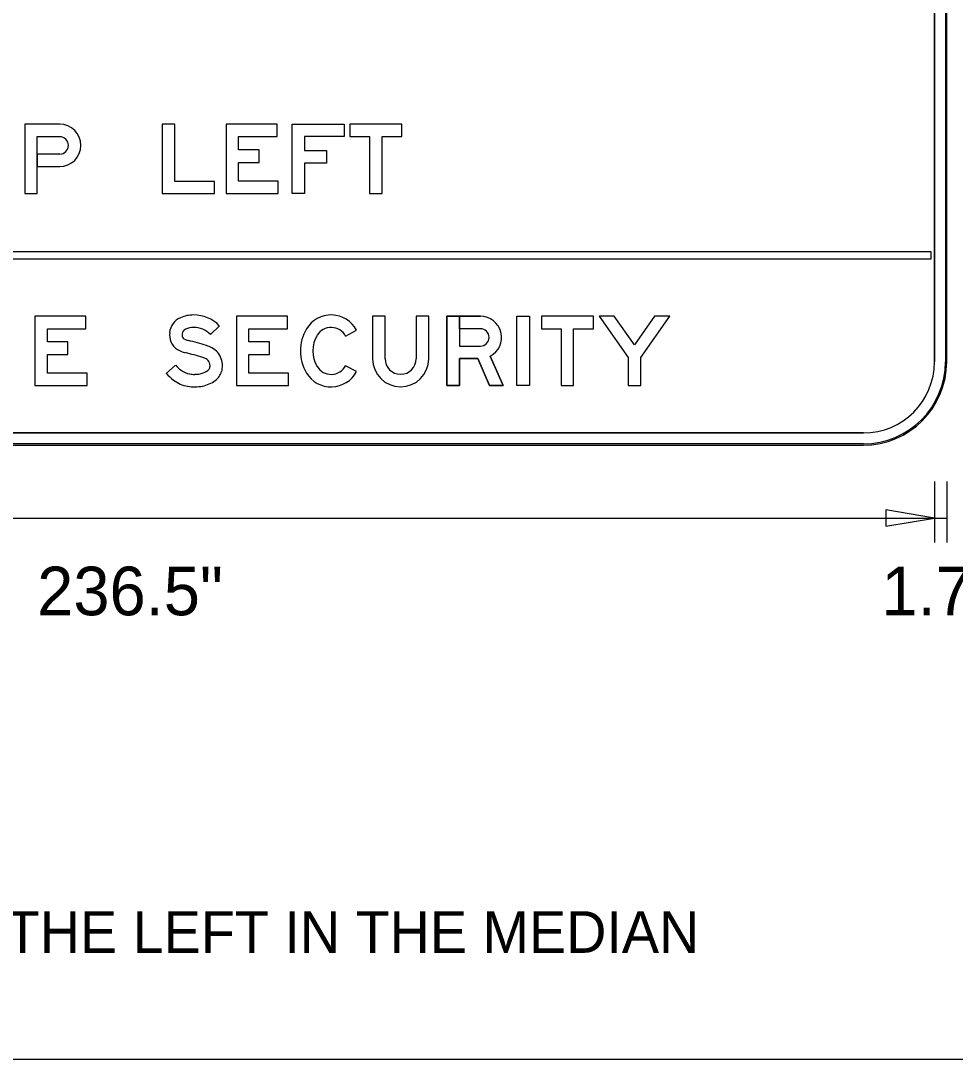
# Model space of a CAD drawing. Extents: x 17890071 to 17890754, y 17897628 to 17897992.
# Drawn here: x 17890123.33 to 17890134.54, y 17897797.14 to 17897809.61 of the extents above; entities that cross this region are included whole.
import ezdxf

# ---------------------------------------------------------------- set-up
doc = ezdxf.new("R2010")
doc.units = 0
for name, color, linetype in [('GSBWFill', 7, 'Continuous'), ('GSColorFill', 7, 'Continuous'), ('GSDims', 7, 'Continuous'), ('GSOutline', 7, 'Continuous'), ('SheetLinesMisc2_dp', 7, 'Continuous')]:
    doc.layers.add(name, color=color, linetype=linetype)

msp = doc.modelspace()

# ---------------------------------------------------------------- linework, layer by layer
at = {"layer": 'GSBWFill'}
for p, q in [((17890134.293, 17897813.514), (17890134.293, 17897805.514)), ((17890134.439, 17897805.514), (17890134.439, 17897813.514)), ((17890123.528, 17897808.216), (17890123.798, 17897808.216)), ((17890134.253, 17897806.832), (17890114.587, 17897806.832)), ((17890134.253, 17897806.749), (17890134.253, 17897806.832)), ((17890114.587, 17897806.749), (17890134.253, 17897806.749)), ((17890128.076, 17897806.061), (17890128.076, 17897805.551)), ((17890127.227, 17897805.822), (17890127.359, 17897805.892)), ((17890127.359, 17897805.397), (17890127.227, 17897805.467)), ((17890127.227, 17897805.467), (17890127.227, 17897805.467)), ((17890133.439, 17897804.66), (17890115.441, 17897804.66)), ((17890115.441, 17897804.514), (17890133.439, 17897804.514))]:
    msp.add_line(p, q, dxfattribs=at)
for points in [[(17890123.798, 17897808.366), (17890123.378, 17897808.366), (17890123.378, 17897807.532), (17890123.528, 17897807.532), (17890123.528, 17897808.216)], [(17890123.798, 17897808.007), (17890123.528, 17897808.007), (17890123.528, 17897807.857), (17890123.798, 17897807.857)], [(17890127.701, 17897805.551), (17890127.701, 17897806.061), (17890127.551, 17897806.061), (17890127.551, 17897805.551)], [(17890128.226, 17897805.551), (17890128.226, 17897806.061), (17890128.076, 17897806.061)], [(17890128.964, 17897805.582), (17890129.118, 17897805.228), (17890128.954, 17897805.228), (17890128.813, 17897805.553), (17890128.593, 17897805.553), (17890128.593, 17897805.228), (17890128.443, 17897805.228), (17890128.443, 17897806.061), (17890128.593, 17897806.061), (17890128.593, 17897805.703), (17890128.845, 17897805.703)], [(17890128.593, 17897805.911), (17890128.593, 17897806.061), (17890128.845, 17897806.061)], [(17890125.713, 17897805.946), (17890125.605, 17897805.841)], [(17890128.845, 17897805.911), (17890128.593, 17897805.911)], [(17890125.076, 17897805.375), (17890125.189, 17897805.474)]]:
    msp.add_lwpolyline(points, dxfattribs=at)
for points in [[(17890125.653, 17897807.532), (17890125.653, 17897807.678), (17890125.178, 17897807.678), (17890125.178, 17897808.366), (17890125.028, 17897808.366), (17890125.028, 17897807.532)], [(17890126.419, 17897807.682), (17890125.944, 17897807.682), (17890125.944, 17897807.906), (17890126.19, 17897807.906), (17890126.19, 17897808.056), (17890125.944, 17897808.056), (17890125.944, 17897808.216), (17890126.407, 17897808.216), (17890126.407, 17897808.366), (17890125.794, 17897808.366), (17890125.794, 17897807.532), (17890126.419, 17897807.532)], [(17890126.736, 17897807.899), (17890126.736, 17897807.532), (17890126.586, 17897807.532), (17890126.586, 17897808.366), (17890127.211, 17897808.366), (17890127.211, 17897808.216), (17890126.736, 17897808.216), (17890126.736, 17897808.049), (17890126.998, 17897808.049), (17890126.998, 17897807.899)], [(17890127.278, 17897808.216), (17890127.515, 17897808.216), (17890127.515, 17897807.532), (17890127.665, 17897807.532), (17890127.665, 17897808.216), (17890127.903, 17897808.216), (17890127.903, 17897808.366), (17890127.278, 17897808.366)], [(17890124.126, 17897805.378), (17890123.651, 17897805.378), (17890123.651, 17897805.602), (17890123.897, 17897805.602), (17890123.897, 17897805.752), (17890123.651, 17897805.752), (17890123.651, 17897805.911), (17890124.113, 17897805.911), (17890124.113, 17897806.061), (17890123.501, 17897806.061), (17890123.501, 17897805.228), (17890124.126, 17897805.228)], [(17890126.543, 17897805.378), (17890126.068, 17897805.378), (17890126.068, 17897805.602), (17890126.313, 17897805.602), (17890126.313, 17897805.752), (17890126.068, 17897805.752), (17890126.068, 17897805.911), (17890126.53, 17897805.911), (17890126.53, 17897806.061), (17890125.918, 17897806.061), (17890125.918, 17897805.228), (17890126.543, 17897805.228)], [(17890129.284, 17897805.228), (17890129.284, 17897806.061), (17890129.434, 17897806.061), (17890129.434, 17897805.228)], [(17890129.576, 17897805.911), (17890129.813, 17897805.911), (17890129.813, 17897805.228), (17890129.963, 17897805.228), (17890129.963, 17897805.911), (17890130.201, 17897805.911), (17890130.201, 17897806.061), (17890129.576, 17897806.061)], [(17890130.768, 17897805.565), (17890131.118, 17897806.061), (17890130.934, 17897806.061), (17890130.693, 17897805.719), (17890130.451, 17897806.061), (17890130.268, 17897806.061), (17890130.618, 17897805.565), (17890130.618, 17897805.228), (17890130.768, 17897805.228)]]:
    msp.add_lwpolyline(points, close=True, dxfattribs=at)
for centre, radius, start, end in [((17890125.405, 17897805.678), 0.398, 90, 113.3248), ((17890125.405, 17897805.645), 0.431, 44.4342, 90), ((17890127.054, 17897805.73), 0.346, 28.0265, 148.7499), ((17890125.333, 17897805.843), 0.218, 113.3248, 174.1421), ((17890128.845, 17897805.807), 0.254, 297.837, 90), ((17890125.354, 17897805.841), 0.238, 174.1421, 201.2247), ((17890125.354, 17897805.841), 0.0882, 174.1421, 201.2247), ((17890125.333, 17897805.843), 0.0679, 113.3248, 174.1421), ((17890125.405, 17897805.678), 0.248, 90, 113.3248), ((17890125.405, 17897805.645), 0.281, 44.4342, 90), ((17890127.195, 17897805.644), 0.51, 148.7499, 211.2501), ((17890127.195, 17897805.644), 0.36, 148.7499, 211.2501), ((17890127.054, 17897805.73), 0.196, 28.0265, 148.7499), ((17890128.845, 17897805.807), 0.104, 270, 90), ((17890125.305, 17897805.822), 0.186, 201.2247, 240.1812), ((17890125.305, 17897805.822), 0.0363, 201.2247, 240.1812), ((17890125.391, 17897805.972), 0.209, 240.1812, 256.1067), ((17890124.37, 17897801.843), 4.045, 72.8961, 76.1067), ((17890125.442, 17897805.326), 0.4, 63.0108, 72.8961), ((17890125.391, 17897805.972), 0.359, 240.1812, 256.1067), ((17890124.37, 17897801.843), 3.895, 72.8961, 76.1067), ((17890125.522, 17897805.485), 0.222, 39.5561, 63.0108), ((17890125.502, 17897805.467), 0.249, 0, 39.5561), ((17890125.515, 17897805.755), 0.43, 220.8202, 232.6492), ((17890125.442, 17897805.326), 0.25, 63.0108, 72.8961), ((17890125.522, 17897805.485), 0.0724, 39.5561, 63.0108), ((17890125.502, 17897805.467), 0.0993, 0, 39.5561), ((17890125.508, 17897805.467), 0.0932, 343.4972, 0), ((17890125.508, 17897805.467), 0.243, 343.4972, 0), ((17890127.054, 17897805.559), 0.196, 211.2501, 331.9735), ((17890127.888, 17897805.551), 0.337, 180, 0), ((17890127.888, 17897805.551), 0.187, 180, 0), ((17890133.439, 17897805.514), 1, 270, 0), ((17890133.439, 17897805.514), 0.854, 270, 0), ((17890125.515, 17897805.755), 0.58, 220.8202, 232.6492), ((17890125.394, 17897805.597), 0.231, 232.6492, 260.7349), ((17890125.42, 17897805.751), 0.388, 260.7349, 270), ((17890125.42, 17897805.67), 0.306, 270, 281.6446), ((17890125.432, 17897805.609), 0.245, 281.6446, 306.0677), ((17890125.543, 17897805.457), 0.0563, 306.0677, 343.4972), ((17890125.543, 17897805.457), 0.206, 306.0677, 343.4972), ((17890127.054, 17897805.559), 0.346, 211.2501, 331.9735), ((17890125.394, 17897805.597), 0.381, 232.6492, 260.7349), ((17890125.42, 17897805.751), 0.538, 260.7349, 270), ((17890125.42, 17897805.67), 0.456, 270, 281.6446), ((17890125.432, 17897805.609), 0.395, 281.6446, 306.0677)]:
    msp.add_arc(centre, radius, start, end, dxfattribs=at)
for major_axis in [(0, 0.254), (0, 0.104)]:
    msp.add_ellipse((17890123.798, 17897808.111), major_axis=major_axis, ratio=0.999997, start_param=3.141593, end_param=6.283185, dxfattribs=at)
at = {"layer": 'GSColorFill'}
for p, q in [((17890134.293, 17897813.514), (17890134.293, 17897805.514)), ((17890134.425, 17897813.514), (17890134.425, 17897805.514)), ((17890134.439, 17897805.514), (17890134.439, 17897813.514)), ((17890134.439, 17897805.514), (17890134.439, 17897813.514)), ((17890134.439, 17897805.514), (17890134.439, 17897813.514)), ((17890123.528, 17897808.216), (17890123.798, 17897808.216)), ((17890134.253, 17897806.832), (17890114.587, 17897806.832)), ((17890134.253, 17897806.749), (17890134.253, 17897806.832)), ((17890114.587, 17897806.749), (17890134.253, 17897806.749)), ((17890128.076, 17897806.061), (17890128.076, 17897805.551)), ((17890127.227, 17897805.822), (17890127.359, 17897805.892)), ((17890127.359, 17897805.397), (17890127.227, 17897805.467)), ((17890127.227, 17897805.467), (17890127.227, 17897805.467)), ((17890133.439, 17897804.66), (17890115.441, 17897804.66)), ((17890133.439, 17897804.529), (17890115.439, 17897804.529)), ((17890115.439, 17897804.514), (17890133.439, 17897804.514)), ((17890115.439, 17897804.514), (17890133.439, 17897804.514)), ((17890115.441, 17897804.514), (17890133.439, 17897804.514))]:
    msp.add_line(p, q, dxfattribs=at)
for points in [[(17890123.798, 17897808.366), (17890123.378, 17897808.366), (17890123.378, 17897807.532), (17890123.528, 17897807.532), (17890123.528, 17897808.216)], [(17890123.798, 17897808.007), (17890123.528, 17897808.007), (17890123.528, 17897807.857), (17890123.798, 17897807.857)], [(17890127.701, 17897805.551), (17890127.701, 17897806.061), (17890127.551, 17897806.061), (17890127.551, 17897805.551)], [(17890128.226, 17897805.551), (17890128.226, 17897806.061), (17890128.076, 17897806.061)], [(17890128.964, 17897805.582), (17890129.118, 17897805.228), (17890128.954, 17897805.228), (17890128.813, 17897805.553), (17890128.593, 17897805.553), (17890128.593, 17897805.228), (17890128.443, 17897805.228), (17890128.443, 17897806.061), (17890128.593, 17897806.061), (17890128.593, 17897805.703), (17890128.845, 17897805.703)], [(17890128.593, 17897805.911), (17890128.593, 17897806.061), (17890128.845, 17897806.061)], [(17890125.713, 17897805.946), (17890125.605, 17897805.841)], [(17890128.845, 17897805.911), (17890128.593, 17897805.911)], [(17890125.076, 17897805.375), (17890125.189, 17897805.474)]]:
    msp.add_lwpolyline(points, dxfattribs=at)
for points in [[(17890125.653, 17897807.532), (17890125.653, 17897807.678), (17890125.178, 17897807.678), (17890125.178, 17897808.366), (17890125.028, 17897808.366), (17890125.028, 17897807.532)], [(17890126.419, 17897807.682), (17890125.944, 17897807.682), (17890125.944, 17897807.906), (17890126.19, 17897807.906), (17890126.19, 17897808.056), (17890125.944, 17897808.056), (17890125.944, 17897808.216), (17890126.407, 17897808.216), (17890126.407, 17897808.366), (17890125.794, 17897808.366), (17890125.794, 17897807.532), (17890126.419, 17897807.532)], [(17890126.736, 17897807.899), (17890126.736, 17897807.532), (17890126.586, 17897807.532), (17890126.586, 17897808.366), (17890127.211, 17897808.366), (17890127.211, 17897808.216), (17890126.736, 17897808.216), (17890126.736, 17897808.049), (17890126.998, 17897808.049), (17890126.998, 17897807.899)], [(17890127.278, 17897808.216), (17890127.515, 17897808.216), (17890127.515, 17897807.532), (17890127.665, 17897807.532), (17890127.665, 17897808.216), (17890127.903, 17897808.216), (17890127.903, 17897808.366), (17890127.278, 17897808.366)], [(17890124.126, 17897805.378), (17890123.651, 17897805.378), (17890123.651, 17897805.602), (17890123.897, 17897805.602), (17890123.897, 17897805.752), (17890123.651, 17897805.752), (17890123.651, 17897805.911), (17890124.113, 17897805.911), (17890124.113, 17897806.061), (17890123.501, 17897806.061), (17890123.501, 17897805.228), (17890124.126, 17897805.228)], [(17890126.543, 17897805.378), (17890126.068, 17897805.378), (17890126.068, 17897805.602), (17890126.313, 17897805.602), (17890126.313, 17897805.752), (17890126.068, 17897805.752), (17890126.068, 17897805.911), (17890126.53, 17897805.911), (17890126.53, 17897806.061), (17890125.918, 17897806.061), (17890125.918, 17897805.228), (17890126.543, 17897805.228)], [(17890129.284, 17897805.228), (17890129.284, 17897806.061), (17890129.434, 17897806.061), (17890129.434, 17897805.228)], [(17890129.576, 17897805.911), (17890129.813, 17897805.911), (17890129.813, 17897805.228), (17890129.963, 17897805.228), (17890129.963, 17897805.911), (17890130.201, 17897805.911), (17890130.201, 17897806.061), (17890129.576, 17897806.061)], [(17890130.768, 17897805.565), (17890131.118, 17897806.061), (17890130.934, 17897806.061), (17890130.693, 17897805.719), (17890130.451, 17897806.061), (17890130.268, 17897806.061), (17890130.618, 17897805.565), (17890130.618, 17897805.228), (17890130.768, 17897805.228)]]:
    msp.add_lwpolyline(points, close=True, dxfattribs=at)
for centre, radius, start, end in [((17890125.405, 17897805.678), 0.398, 90, 113.3248), ((17890125.405, 17897805.645), 0.431, 44.4342, 90), ((17890127.054, 17897805.73), 0.346, 28.0265, 148.7499), ((17890125.333, 17897805.843), 0.218, 113.3248, 174.1421), ((17890128.845, 17897805.807), 0.254, 297.837, 90), ((17890125.354, 17897805.841), 0.238, 174.1421, 201.2247), ((17890125.354, 17897805.841), 0.0882, 174.1421, 201.2247), ((17890125.333, 17897805.843), 0.0679, 113.3248, 174.1421), ((17890125.405, 17897805.678), 0.248, 90, 113.3248), ((17890125.405, 17897805.645), 0.281, 44.4342, 90), ((17890127.195, 17897805.644), 0.51, 148.7499, 211.2501), ((17890127.195, 17897805.644), 0.36, 148.7499, 211.2501), ((17890127.054, 17897805.73), 0.196, 28.0265, 148.7499), ((17890128.845, 17897805.807), 0.104, 270, 90), ((17890125.305, 17897805.822), 0.186, 201.2247, 240.1812), ((17890125.305, 17897805.822), 0.0363, 201.2247, 240.1812), ((17890125.391, 17897805.972), 0.209, 240.1812, 256.1067), ((17890124.37, 17897801.843), 4.045, 72.8961, 76.1067), ((17890125.442, 17897805.326), 0.4, 63.0108, 72.8961), ((17890125.391, 17897805.972), 0.359, 240.1812, 256.1067), ((17890124.37, 17897801.843), 3.895, 72.8961, 76.1067), ((17890125.522, 17897805.485), 0.222, 39.5561, 63.0108), ((17890125.502, 17897805.467), 0.249, 0, 39.5561), ((17890125.515, 17897805.755), 0.43, 220.8202, 232.6492), ((17890125.442, 17897805.326), 0.25, 63.0108, 72.8961), ((17890125.522, 17897805.485), 0.0724, 39.5561, 63.0108), ((17890125.502, 17897805.467), 0.0993, 0, 39.5561), ((17890125.508, 17897805.467), 0.0932, 343.4972, 0), ((17890125.508, 17897805.467), 0.243, 343.4972, 0), ((17890127.054, 17897805.559), 0.196, 211.2501, 331.9735), ((17890127.888, 17897805.551), 0.337, 180, 0), ((17890127.888, 17897805.551), 0.187, 180, 0), ((17890133.439, 17897805.514), 1, 270, 0), ((17890133.439, 17897805.514), 1, 270, 0), ((17890133.439, 17897805.514), 0.854, 270, 0), ((17890133.439, 17897805.514), 1, 270, 0), ((17890133.439, 17897805.514), 0.985, 270, 0), ((17890125.515, 17897805.755), 0.58, 220.8202, 232.6492), ((17890125.394, 17897805.597), 0.231, 232.6492, 260.7349), ((17890125.42, 17897805.751), 0.388, 260.7349, 270), ((17890125.42, 17897805.67), 0.306, 270, 281.6446), ((17890125.432, 17897805.609), 0.245, 281.6446, 306.0677), ((17890125.543, 17897805.457), 0.0563, 306.0677, 343.4972), ((17890125.543, 17897805.457), 0.206, 306.0677, 343.4972), ((17890127.054, 17897805.559), 0.346, 211.2501, 331.9735), ((17890125.394, 17897805.597), 0.381, 232.6492, 260.7349), ((17890125.42, 17897805.751), 0.538, 260.7349, 270), ((17890125.42, 17897805.67), 0.456, 270, 281.6446), ((17890125.432, 17897805.609), 0.395, 281.6446, 306.0677)]:
    msp.add_arc(centre, radius, start, end, dxfattribs=at)
for major_axis in [(0, 0.254), (0, 0.104)]:
    msp.add_ellipse((17890123.798, 17897808.111), major_axis=major_axis, ratio=0.999997, start_param=3.141593, end_param=6.283185, dxfattribs=at)
at = {"layer": 'GSDims'}
for p, q in [((17890134.294, 17897804.077), (17890134.294, 17897803.347)), ((17890134.439, 17897804.077), (17890134.439, 17897803.347)), ((17890114.585, 17897803.639), (17890134.273, 17897803.639)), ((17890134.273, 17897803.639), (17890134.294, 17897803.639)), ((17890134.294, 17897803.639), (17890134.439, 17897803.639))]:
    msp.add_line(p, q, dxfattribs=at)
msp.add_lwpolyline([(17890134.294, 17897803.639), (17890133.71, 17897803.736), (17890133.71, 17897803.542)], close=True, dxfattribs=at)
at = {"layer": 'GSOutline'}
for p, q in [((17890134.293, 17897805.514), (17890134.293, 17897813.514)), ((17890134.439, 17897805.514), (17890134.439, 17897813.514)), ((17890123.528, 17897808.216), (17890123.798, 17897808.216)), ((17890123.528, 17897807.857), (17890123.798, 17897807.857)), ((17890134.253, 17897806.832), (17890114.587, 17897806.832)), ((17890134.253, 17897806.749), (17890134.253, 17897806.832)), ((17890114.587, 17897806.749), (17890134.253, 17897806.749)), ((17890128.076, 17897806.061), (17890128.076, 17897805.551)), ((17890127.227, 17897805.822), (17890127.359, 17897805.892)), ((17890127.359, 17897805.397), (17890127.227, 17897805.467)), ((17890127.227, 17897805.467), (17890127.227, 17897805.467)), ((17890115.439, 17897804.66), (17890133.439, 17897804.66)), ((17890115.439, 17897804.514), (17890133.439, 17897804.514))]:
    msp.add_line(p, q, dxfattribs=at)
for points in [[(17890123.798, 17897808.366), (17890123.378, 17897808.366), (17890123.378, 17897807.532), (17890123.528, 17897807.532), (17890123.528, 17897807.857)], [(17890123.798, 17897808.007), (17890123.528, 17897808.007), (17890123.528, 17897808.216)], [(17890127.701, 17897805.551), (17890127.701, 17897806.061), (17890127.551, 17897806.061), (17890127.551, 17897805.551)], [(17890128.226, 17897805.551), (17890128.226, 17897806.061), (17890128.076, 17897806.061)], [(17890128.845, 17897806.061), (17890128.443, 17897806.061), (17890128.443, 17897805.228), (17890128.593, 17897805.228), (17890128.593, 17897805.553), (17890128.813, 17897805.553), (17890128.954, 17897805.228), (17890129.118, 17897805.228), (17890128.964, 17897805.582)], [(17890125.713, 17897805.946), (17890125.605, 17897805.841)], [(17890128.845, 17897805.911), (17890128.593, 17897805.911), (17890128.593, 17897805.703), (17890128.845, 17897805.703)], [(17890125.076, 17897805.375), (17890125.189, 17897805.474)]]:
    msp.add_lwpolyline(points, dxfattribs=at)
for points in [[(17890125.653, 17897807.532), (17890125.653, 17897807.678), (17890125.178, 17897807.678), (17890125.178, 17897808.366), (17890125.028, 17897808.366), (17890125.028, 17897807.532)], [(17890126.419, 17897807.682), (17890125.944, 17897807.682), (17890125.944, 17897807.906), (17890126.19, 17897807.906), (17890126.19, 17897808.056), (17890125.944, 17897808.056), (17890125.944, 17897808.216), (17890126.407, 17897808.216), (17890126.407, 17897808.366), (17890125.794, 17897808.366), (17890125.794, 17897807.532), (17890126.419, 17897807.532)], [(17890126.736, 17897807.899), (17890126.736, 17897807.532), (17890126.586, 17897807.532), (17890126.586, 17897808.366), (17890127.211, 17897808.366), (17890127.211, 17897808.216), (17890126.736, 17897808.216), (17890126.736, 17897808.049), (17890126.998, 17897808.049), (17890126.998, 17897807.899)], [(17890127.278, 17897808.216), (17890127.515, 17897808.216), (17890127.515, 17897807.532), (17890127.665, 17897807.532), (17890127.665, 17897808.216), (17890127.903, 17897808.216), (17890127.903, 17897808.366), (17890127.278, 17897808.366)], [(17890124.126, 17897805.378), (17890123.651, 17897805.378), (17890123.651, 17897805.602), (17890123.897, 17897805.602), (17890123.897, 17897805.752), (17890123.651, 17897805.752), (17890123.651, 17897805.911), (17890124.113, 17897805.911), (17890124.113, 17897806.061), (17890123.501, 17897806.061), (17890123.501, 17897805.228), (17890124.126, 17897805.228)], [(17890126.543, 17897805.378), (17890126.068, 17897805.378), (17890126.068, 17897805.602), (17890126.313, 17897805.602), (17890126.313, 17897805.752), (17890126.068, 17897805.752), (17890126.068, 17897805.911), (17890126.53, 17897805.911), (17890126.53, 17897806.061), (17890125.918, 17897806.061), (17890125.918, 17897805.228), (17890126.543, 17897805.228)], [(17890129.284, 17897805.228), (17890129.284, 17897806.061), (17890129.434, 17897806.061), (17890129.434, 17897805.228)], [(17890129.576, 17897805.911), (17890129.813, 17897805.911), (17890129.813, 17897805.228), (17890129.963, 17897805.228), (17890129.963, 17897805.911), (17890130.201, 17897805.911), (17890130.201, 17897806.061), (17890129.576, 17897806.061)], [(17890130.768, 17897805.565), (17890131.118, 17897806.061), (17890130.934, 17897806.061), (17890130.693, 17897805.719), (17890130.451, 17897806.061), (17890130.268, 17897806.061), (17890130.618, 17897805.565), (17890130.618, 17897805.228), (17890130.768, 17897805.228)]]:
    msp.add_lwpolyline(points, close=True, dxfattribs=at)
for centre, radius, start, end in [((17890125.405, 17897805.678), 0.398, 90, 113.3248), ((17890125.405, 17897805.645), 0.431, 44.4342, 90), ((17890127.054, 17897805.73), 0.346, 28.0265, 148.7499), ((17890125.333, 17897805.843), 0.218, 113.3248, 174.1421), ((17890128.845, 17897805.807), 0.254, 297.837, 90), ((17890125.354, 17897805.841), 0.238, 174.1421, 201.2247), ((17890125.354, 17897805.841), 0.0882, 174.1421, 201.2247), ((17890125.333, 17897805.843), 0.0679, 113.3248, 174.1421), ((17890125.405, 17897805.678), 0.248, 90, 113.3248), ((17890125.405, 17897805.645), 0.281, 44.4342, 90), ((17890127.195, 17897805.644), 0.51, 148.7499, 211.2501), ((17890127.195, 17897805.644), 0.36, 148.7499, 211.2501), ((17890127.054, 17897805.73), 0.196, 28.0265, 148.7499), ((17890128.845, 17897805.807), 0.104, 270, 90), ((17890125.305, 17897805.822), 0.186, 201.2247, 240.1812), ((17890125.305, 17897805.822), 0.0363, 201.2247, 240.1812), ((17890125.391, 17897805.972), 0.209, 240.1812, 256.1067), ((17890124.37, 17897801.843), 4.045, 72.8961, 76.1067), ((17890125.442, 17897805.326), 0.4, 63.0108, 72.8961), ((17890125.391, 17897805.972), 0.359, 240.1812, 256.1067), ((17890124.37, 17897801.843), 3.895, 72.8961, 76.1067), ((17890125.522, 17897805.485), 0.222, 39.5561, 63.0108), ((17890125.502, 17897805.467), 0.249, 0, 39.5561), ((17890125.515, 17897805.755), 0.43, 220.8202, 232.6492), ((17890125.442, 17897805.326), 0.25, 63.0108, 72.8961), ((17890125.522, 17897805.485), 0.0724, 39.5561, 63.0108), ((17890125.502, 17897805.467), 0.0993, 0, 39.5561), ((17890125.508, 17897805.467), 0.0932, 343.4972, 0), ((17890125.508, 17897805.467), 0.243, 343.4972, 0), ((17890127.054, 17897805.559), 0.196, 211.2501, 331.9735), ((17890127.888, 17897805.551), 0.337, 180, 0), ((17890127.888, 17897805.551), 0.187, 180, 0), ((17890133.439, 17897805.514), 1, 270, 0), ((17890133.439, 17897805.514), 0.854, 270, 0), ((17890125.515, 17897805.755), 0.58, 220.8202, 232.6492), ((17890125.394, 17897805.597), 0.231, 232.6492, 260.7349), ((17890125.42, 17897805.751), 0.388, 260.7349, 270), ((17890125.42, 17897805.67), 0.306, 270, 281.6446), ((17890125.432, 17897805.609), 0.245, 281.6446, 306.0677), ((17890125.543, 17897805.457), 0.0563, 306.0677, 343.4972), ((17890125.543, 17897805.457), 0.206, 306.0677, 343.4972), ((17890127.054, 17897805.559), 0.346, 211.2501, 331.9735), ((17890125.394, 17897805.597), 0.381, 232.6492, 260.7349), ((17890125.42, 17897805.751), 0.538, 260.7349, 270), ((17890125.42, 17897805.67), 0.456, 270, 281.6446), ((17890125.432, 17897805.609), 0.395, 281.6446, 306.0677)]:
    msp.add_arc(centre, radius, start, end, dxfattribs=at)
for major_axis in [(0, 0.254), (0, 0.104)]:
    msp.add_ellipse((17890123.798, 17897808.111), major_axis=major_axis, ratio=0.999997, start_param=3.141593, end_param=6.283185, dxfattribs=at)
at = {"layer": 'SheetLinesMisc2_dp'}
msp.add_line((17890100.188, 17897797.144), (17890151.359, 17897797.144), dxfattribs=at)

# ---------------------------------------------------------------- texts
at = {"layer": 'GSDims'}
for s, height, p in [('236.5"', 0.5833, (17890123.528, 17897802.472)), ('1.75"', 0.5833, (17890133.657, 17897802.472)), ('TYPICAL: FINAL SIGN BEFORE ENTRY TO THE PLAZA. INSTALLED ON THE LEFT IN THE MEDIAN', 0.5, (17890100.561, 17897798.421))]:
    msp.add_text(s, height=height, dxfattribs=at).set_placement(p)

doc.saveas('drawing.dxf')
